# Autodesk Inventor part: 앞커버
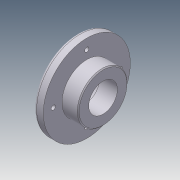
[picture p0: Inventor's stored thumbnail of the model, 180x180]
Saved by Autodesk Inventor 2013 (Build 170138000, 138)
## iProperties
Company: 한국ATC센터
Created: 2014-11
Part Number: 앞커버
Document SubType Name: Modeling
Designer: KYOUNG IL JANG
Density: 2.71 g/cm^3
Material: Aluminum-6061
Mass: 204.895 g
Surface Area: 201.401 cm^2
Volume: 75.6071 cm^3
Author: KYOUNG IL JANG
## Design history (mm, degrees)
revolve "회전1" stored, may be unused: angle "d4" = 90 deg
hole "구멍1" diameter "d7" = 30; stored, may be unused: countersink angle "d11" = 90 deg, drill point angle "d13" = 118 deg; dims "d5" = 10, "d6" = 10, "d8" = 6, "d9" = 40, "d10" = 8.3, "d12" = 8
sketch "스케치2"
  geometry: 2 further points
  constraints: 1 vertical alignment
  dimensions: "d14" = 35 distance of point (0, 0) point (0, 35)
hole "구멍2" sketch "스케치2" diameter "d15" = 4.5; stored, may be unused: countersink angle "d19" = 90 deg, drill point angle "d21" = 118 deg; dims "d16" = 6, "d17" = 8, "d18" = 4.4, "d20" = 8
chamfer "모따기1" distance "d25" = 0.8; stored, may be unused: second distance "d26" = 2, angle "d27" = 30 deg
fillet "모깎기1" dims "d28" = 0.3, "d29" = 3
chamfer "모따기2" distance "d30" = 1; stored, may be unused: second distance "d31" = 2, angle "d32" = 30 deg
node "솔리드1"
pattern_circular "원형 패턴1" dims angle "d23" = 360 deg
sketch "스케치1"
  geometry: L1 (-13.5, 0)-(13.5, 0); L2 (-13.5, 0)-(-13.5, 45.5); L3 (-13.5, 45.5)-(-3.5, 45.5); L4 (-3.5, 45.5)-(-3.5, 26); L5 (-3.5, 26)-(13.5, 26); L6 (13.5, 26)-(13.5, 0); 2 further points
  constraints: 12 end point, 3 parallel, 2 perpendicular, 1 coincident, 1 horizontal, 1 midpoint
  dimensions: "d0" = 27 distance of L1.start L1.end; "d1" = 91 diameter of L3 L1; "d2" = 52 diameter of L5 L1; "d3" = 10 distance of L2.end L3.end
